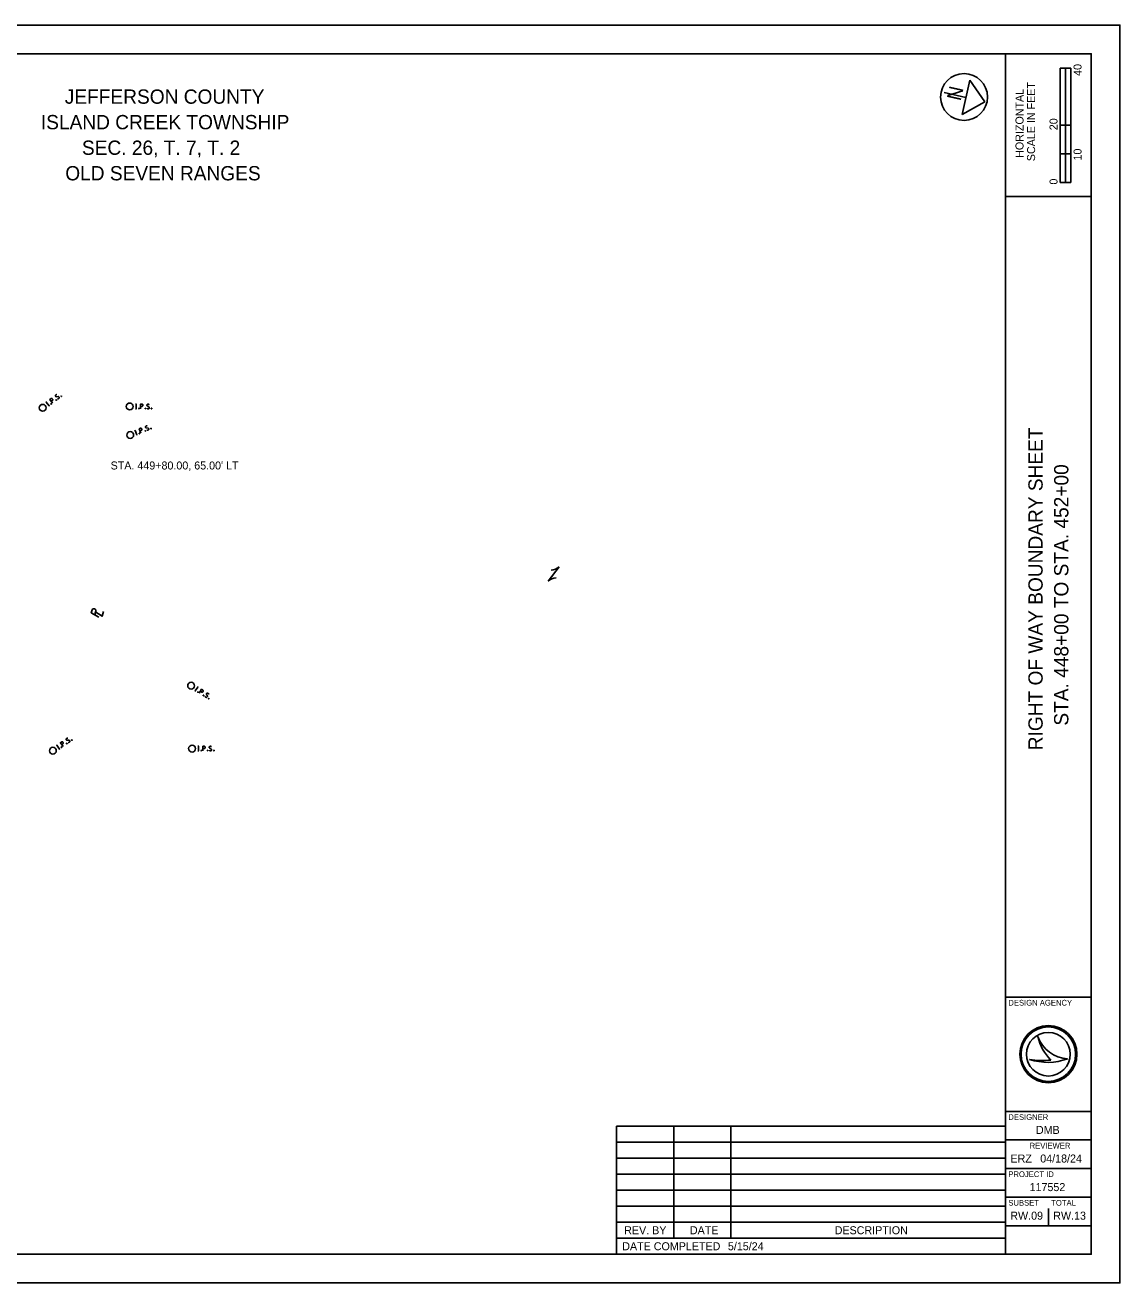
# Model space of a CAD drawing. Extents: x 0 to 116195, y -227 to 408682.
# Drawn here: x 297.1 to 680, y 0 to 440 of the extents above; entities that cross this region are included whole.
import ezdxf

# ---------------------------------------------------------------- set-up
doc = ezdxf.new("R2010")
doc.units = 0
for name, color, linetype in [('_CIVIL_CONSTRUCTION', 7, 'Continuous'), ('CM_Corridor_Final', 7, 'Continuous'), ('CM_Corridor_Range_Final', 7, 'Continuous'), ('MD_P_ACB_B', 7, 'Continuous'), ('MD_P_ACB_T', 7, 'Continuous'), ('MD_P_ACIC_B', 7, 'Continuous'), ('PV_P_EOP', 7, 'Continuous')]:
    doc.layers.add(name, color=color, linetype=linetype)

msp = doc.modelspace()

# ---------------------------------------------------------------- linework, layer by layer
at = {"layer": '_CIVIL_CONSTRUCTION'}
msp.add_lwpolyline([(0, 0), (680, 0), (680, 440), (0, 440)], close=True, dxfattribs=at)
at = {"layer": 'CM_Corridor_Final'}
for p, q in [((659.13, 385), (659.13, 425)), ((662.88, 425), (659.13, 425)), ((659.13, 405), (659.13, 425)), ((659.13, 425), (661, 425)), ((661, 425), (661.02, 425)), ((661.02, 425), (661.02, 405)), ((662.88, 425), (662.88, 385)), ((661.02, 405), (659.13, 405)), ((662.87, 405), (661, 405)), ((661, 405), (661, 395)), ((662.87, 395), (662.87, 405)), ((661, 395), (659.13, 395)), ((659.13, 395), (659.13, 385)), ((661, 385), (661, 395)), ((661, 395), (662.87, 395)), ((662.88, 385), (659.13, 385)), ((659.13, 385), (661, 385)), ((651.35, 86.19), (651.35, 86.19)), ((655, 80), (655, 80)), ((648.34, 78.19), (648.34, 78.19)), ((661.75, 78.37), (661.75, 78.37)), ((655, 20), (655, 26))]:
    msp.add_line(p, q, dxfattribs=at)
for radius in [10, 9.54, 9.54, 7.64]:
    msp.add_circle((655, 80), radius, dxfattribs=at)
for centre, radius, start, end in [((662.32, 89.95), 11.6, 198.9257, 198.9319), ((666.93, 89.4), 15.91, 191.6379, 191.6421), ((662.32, 89.95), 11.6, 198.9319, 267.1657), ((666.93, 89.4), 15.91, 191.6421, 226.0947), ((654.79, 97.4), 20.26, 251.4576, 290.0832), ((652.96, 103.09), 25.32, 259.4964, 259.4995), ((654.79, 97.4), 20.26, 251.4527, 251.4576), ((652.96, 103.09), 25.32, 259.4995, 276.6672)]:
    msp.add_arc(centre, radius, start, end, dxfattribs=at)
at = {"layer": 'CM_Corridor_Range_Final'}
for p, q in [((640, 10), (640, 430)), ((640, 380), (670, 380)), ((640, 100), (670, 100)), ((640, 60), (670, 60)), ((640, 50), (670, 50)), ((640, 40), (670, 40)), ((640, 30), (670, 30)), ((640, 20), (670, 20))]:
    msp.add_line(p, q, dxfattribs=at)
msp.add_lwpolyline([(30, 430), (670, 430), (670, 10), (30, 10)], close=True, dxfattribs=at)
at = {"layer": 'MD_P_ACB_B'}
msp.add_circle((625.5, 414.86), 8.2, dxfattribs=at)
at = {"layer": 'MD_P_ACB_T'}
for p, q in [((480.03, 245.5), (483.84, 250.45)), ((481.93, 247.98), (481.93, 247.98)), ((321.39, 233.7), (321.77, 234.94)), ((322.22, 234.28), (322.22, 234.28))]:
    msp.add_line(p, q, dxfattribs=at)
for points in [[(322.79, 232.83), (320.18, 234.45), (320.49, 235.43)], [(321.38, 234.82), (323.97, 233.19), (324.49, 234.86)]]:
    msp.add_lwpolyline(points, dxfattribs=at)
for centre, radius, start, end in [((483.35, 241.33), 5.34, 95.9058, 128.5484), ((480.51, 254.63), 5.34, 275.9058, 308.5484), ((321.11, 235.13), 0.69, 343.4196, 154.2767)]:
    msp.add_arc(centre, radius, start, end, dxfattribs=at)
at = {"layer": 'MD_P_ACIC_B'}
for p, q in [((627.48, 420.72), (624.79, 408.71)), ((632.8, 413.22), (627.48, 420.72)), ((626.14, 414.71), (618.59, 416.41)), ((624.79, 408.71), (632.8, 413.22)), ((503.93, 54.8), (503.93, 10)), ((503.93, 54.8), (640, 54.8)), ((523.93, 54.8), (523.93, 15.6)), ((543.93, 54.8), (543.93, 15.6)), ((503.93, 49.2), (640, 49.2)), ((503.93, 43.6), (640, 43.6)), ((503.93, 38), (640, 38)), ((503.93, 32.4), (640, 32.4)), ((503.93, 26.8), (640, 26.8)), ((503.93, 21.2), (640, 21.2)), ((503.93, 15.6), (640, 15.6)), ((640, 10), (640, 10))]:
    msp.add_line(p, q, dxfattribs=at)
msp.add_circle((625.5, 414.86), 8.2, dxfattribs=at)
at = {"layer": 'PV_P_EOP'}
for points in [[(304.31, 307.99), (304.59, 308.21)], [(305.42, 306.82), (304.45, 308.1)], [(306.67, 307.77), (305.7, 309.04), (306.12, 309.36), (306.17, 309.39), (306.25, 309.41), (306.29, 309.41), (306.33, 309.41), (306.41, 309.39), (306.47, 309.36), (306.55, 309.29), (306.64, 309.17), (306.66, 309.12), (306.69, 309.05), (306.71, 308.95), (306.7, 308.9), (306.68, 308.86), (306.66, 308.8), (306.59, 308.74), (306.17, 308.42)], [(308.17, 310.77), (308.14, 310.77), (308.09, 310.77), (307.99, 310.75), (307.88, 310.69), (307.81, 310.64), (307.78, 310.62), (307.69, 310.5), (307.64, 310.37), (307.64, 310.24), (307.68, 310.15), (307.73, 310.09), (307.81, 310.02), (307.93, 310), (308.64, 310.07), (308.72, 310.06), (308.76, 310.03), (308.83, 309.99), (308.87, 309.93), (308.91, 309.86), (308.93, 309.81), (308.95, 309.75), (308.97, 309.7), (308.97, 309.65), (308.97, 309.6), (308.96, 309.56), (308.94, 309.52), (308.92, 309.49), (308.85, 309.42), (308.72, 309.32), (308.63, 309.28), (308.46, 309.27), (308.34, 309.27)], [(307.85, 308.93), (307.89, 308.96), (307.93, 308.96), (307.99, 308.94), (308.03, 308.89), (308.03, 308.83), (308.02, 308.79), (307.98, 308.76), (307.93, 308.76), (307.88, 308.78), (307.84, 308.83), (307.83, 308.89), (307.85, 308.93)], [(309.59, 310.25), (309.63, 310.28), (309.67, 310.28), (309.73, 310.26), (309.77, 310.21), (309.77, 310.15), (309.76, 310.11), (309.72, 310.07), (309.67, 310.07), (309.62, 310.1), (309.58, 310.15), (309.58, 310.21), (309.59, 310.25)], [(305.28, 306.72), (305.56, 306.93)], [(306.05, 307.57), (306.1, 307.61), (306.14, 307.61), (306.19, 307.59), (306.23, 307.53), (306.24, 307.47), (306.23, 307.43), (306.18, 307.4), (306.14, 307.4), (306.08, 307.42), (306.05, 307.47), (306.04, 307.53), (306.05, 307.57)], [(335.66, 307.4), (336.01, 307.4)], [(335.66, 305.8), (336.01, 305.8)], [(335.84, 305.8), (335.84, 307.4)], [(336.8, 306.01), (336.85, 306.01), (336.88, 305.99), (336.92, 305.94), (336.92, 305.87), (336.88, 305.82), (336.85, 305.8), (336.8, 305.8), (336.76, 305.82), (336.73, 305.87), (336.73, 305.94), (336.76, 305.99), (336.8, 306.01)], [(337.4, 305.8), (337.4, 307.4), (337.93, 307.4), (337.99, 307.38), (338.06, 307.36), (338.1, 307.33), (338.13, 307.31), (338.17, 307.25), (338.21, 307.18), (338.23, 307.08), (338.23, 306.93), (338.22, 306.88), (338.2, 306.8), (338.15, 306.72), (338.11, 306.68), (338.07, 306.65), (338.02, 306.63), (337.93, 306.62), (337.4, 306.62)], [(339.04, 306.01), (339.1, 306.01), (339.13, 305.99), (339.17, 305.94), (339.17, 305.87), (339.13, 305.82), (339.1, 305.8), (339.04, 305.8), (339.01, 305.82), (338.98, 305.87), (338.98, 305.94), (339.01, 305.99), (339.04, 306.01)], [(340.41, 307.28), (340.39, 307.31), (340.36, 307.33), (340.26, 307.37), (340.14, 307.4), (340.05, 307.4), (340.01, 307.4), (339.87, 307.36), (339.75, 307.28), (339.67, 307.18), (339.65, 307.08), (339.65, 307.01), (339.67, 306.91), (339.76, 306.82), (340.37, 306.44), (340.42, 306.39), (340.44, 306.34), (340.47, 306.26), (340.47, 306.19), (340.45, 306.11), (340.44, 306.06), (340.42, 306), (340.4, 305.95), (340.38, 305.91), (340.34, 305.87), (340.31, 305.85), (340.27, 305.82), (340.23, 305.81), (340.14, 305.8), (339.98, 305.8), (339.88, 305.82), (339.74, 305.91), (339.65, 305.99)], [(341.23, 306.01), (341.28, 306.01), (341.31, 305.99), (341.35, 305.94), (341.35, 305.87), (341.31, 305.82), (341.28, 305.8), (341.23, 305.8), (341.19, 305.82), (341.16, 305.87), (341.16, 305.94), (341.19, 305.99), (341.23, 306.01)], [(339.79, 299.82), (339.76, 299.83), (339.72, 299.84), (339.61, 299.84), (339.49, 299.82), (339.41, 299.78), (339.38, 299.77), (339.26, 299.68), (339.18, 299.56), (339.14, 299.44), (339.16, 299.34), (339.19, 299.27), (339.25, 299.18), (339.36, 299.14), (340.07, 299.02), (340.14, 298.99), (340.18, 298.96), (340.23, 298.89), (340.26, 298.82), (340.27, 298.75), (340.28, 298.7), (340.29, 298.63), (340.29, 298.58), (340.28, 298.53), (340.26, 298.49), (340.24, 298.45), (340.21, 298.41), (340.19, 298.39), (340.1, 298.34), (339.96, 298.28), (339.86, 298.26), (339.69, 298.29), (339.58, 298.33)], [(335.35, 298.11), (335.68, 298.24)], [(336.13, 296.7), (335.51, 298.17)], [(335.96, 296.63), (336.29, 296.76)], [(336.93, 297.26), (336.98, 297.28), (337.02, 297.27), (337.07, 297.24), (337.1, 297.18), (337.08, 297.12), (337.06, 297.08), (337.01, 297.06), (336.97, 297.07), (336.92, 297.11), (336.9, 297.16), (336.91, 297.22), (336.93, 297.26)], [(337.57, 297.29), (336.96, 298.77), (337.45, 298.97), (337.51, 298.98), (337.59, 298.99), (337.63, 298.98), (337.67, 298.97), (337.73, 298.93), (337.79, 298.88), (337.85, 298.8), (337.9, 298.66), (337.91, 298.61), (337.92, 298.53), (337.91, 298.43), (337.89, 298.38), (337.87, 298.34), (337.83, 298.3), (337.75, 298.25), (337.26, 298.05)], [(339.01, 298.12), (339.06, 298.14), (339.1, 298.13), (339.15, 298.09), (339.17, 298.04), (339.16, 297.98), (339.14, 297.94), (339.09, 297.92), (339.05, 297.93), (339, 297.96), (338.98, 298.02), (338.99, 298.08), (339.01, 298.12)], [(341.03, 298.95), (341.08, 298.97), (341.12, 298.96), (341.17, 298.93), (341.19, 298.87), (341.18, 298.81), (341.16, 298.77), (341.11, 298.75), (341.07, 298.76), (341.02, 298.8), (340.99, 298.86), (341.01, 298.92), (341.03, 298.95)], [(356.43, 207.18), (356.73, 206.99)], [(356.58, 207.09), (357.41, 208.45)], [(357.26, 208.55), (357.56, 208.36)], [(357.92, 206.27), (358.75, 207.64), (359.2, 207.37), (359.24, 207.33), (359.29, 207.27), (359.31, 207.23), (359.32, 207.19), (359.33, 207.11), (359.33, 207.04), (359.29, 206.94), (359.21, 206.81), (359.18, 206.78), (359.12, 206.72), (359.04, 206.67), (358.98, 206.66), (358.94, 206.66), (358.88, 206.66), (358.8, 206.7), (358.34, 206.97)], [(357.51, 206.77), (357.56, 206.74), (357.57, 206.7), (357.58, 206.64), (357.54, 206.59), (357.49, 206.56), (357.45, 206.56), (357.4, 206.59), (357.38, 206.63), (357.38, 206.69), (357.42, 206.74), (357.47, 206.77), (357.51, 206.77)], [(359.43, 205.6), (359.48, 205.58), (359.5, 205.54), (359.5, 205.48), (359.46, 205.42), (359.41, 205.4), (359.37, 205.39), (359.32, 205.42), (359.31, 205.46), (359.3, 205.52), (359.34, 205.57), (359.39, 205.6), (359.43, 205.6)], [(361.26, 205.98), (361.26, 206.02), (361.24, 206.05), (361.18, 206.14), (361.09, 206.22), (361.01, 206.27), (360.98, 206.29), (360.84, 206.33), (360.7, 206.33), (360.58, 206.28), (360.51, 206.21), (360.47, 206.14), (360.43, 206.04), (360.46, 205.92), (360.79, 205.28), (360.81, 205.21), (360.8, 205.16), (360.78, 205.08), (360.74, 205.02), (360.69, 204.96), (360.66, 204.92), (360.6, 204.88), (360.56, 204.85), (360.52, 204.83), (360.47, 204.81), (360.43, 204.81), (360.38, 204.81), (360.35, 204.81), (360.25, 204.86), (360.12, 204.94), (360.05, 205.01), (359.97, 205.16), (359.94, 205.27)], [(361.3, 204.47), (361.35, 204.44), (361.36, 204.4), (361.36, 204.34), (361.33, 204.29), (361.28, 204.26), (361.23, 204.26), (361.19, 204.29), (361.17, 204.33), (361.17, 204.39), (361.2, 204.44), (361.26, 204.47), (361.3, 204.47)], [(310.3, 187.65), (309.39, 188.96), (309.83, 189.26), (309.88, 189.29), (309.96, 189.31), (310, 189.31), (310.04, 189.3), (310.11, 189.28), (310.18, 189.24), (310.25, 189.17), (310.34, 189.05), (310.36, 189), (310.38, 188.93), (310.4, 188.83), (310.38, 188.77), (310.37, 188.73), (310.34, 188.68), (310.27, 188.62), (309.83, 188.32)], [(311.94, 190.57), (311.91, 190.58), (311.86, 190.58), (311.76, 190.56), (311.65, 190.51), (311.57, 190.46), (311.55, 190.44), (311.45, 190.33), (311.39, 190.2), (311.39, 190.07), (311.42, 189.98), (311.47, 189.92), (311.54, 189.84), (311.67, 189.82), (312.38, 189.85), (312.45, 189.84), (312.5, 189.81), (312.56, 189.76), (312.6, 189.7), (312.64, 189.63), (312.66, 189.59), (312.67, 189.52), (312.68, 189.47), (312.69, 189.42), (312.68, 189.37), (312.67, 189.33), (312.65, 189.29), (312.63, 189.26), (312.55, 189.19), (312.42, 189.11), (312.33, 189.07), (312.16, 189.06), (312.05, 189.07)], [(313.33, 189.99), (313.38, 190.02), (313.42, 190.02), (313.47, 189.99), (313.51, 189.94), (313.51, 189.88), (313.5, 189.84), (313.45, 189.81), (313.41, 189.81), (313.35, 189.84), (313.32, 189.89), (313.32, 189.95), (313.33, 189.99)], [(307.96, 187.98), (308.25, 188.18)], [(309.01, 186.76), (308.1, 188.08)], [(308.86, 186.66), (309.15, 186.86)], [(309.68, 187.48), (309.72, 187.51), (309.76, 187.51), (309.82, 187.49), (309.86, 187.43), (309.86, 187.37), (309.84, 187.33), (309.8, 187.3), (309.76, 187.3), (309.7, 187.33), (309.67, 187.38), (309.66, 187.44), (309.68, 187.48)], [(311.53, 188.75), (311.58, 188.78), (311.62, 188.78), (311.67, 188.76), (311.71, 188.71), (311.71, 188.65), (311.7, 188.61), (311.65, 188.58), (311.61, 188.58), (311.56, 188.6), (311.52, 188.65), (311.52, 188.71), (311.53, 188.75)], [(357.47, 187.71), (357.82, 187.71)], [(357.47, 186.11), (357.82, 186.11)], [(357.64, 186.11), (357.64, 187.71)], [(358.6, 186.33), (358.66, 186.33), (358.69, 186.3), (358.73, 186.25), (358.73, 186.19), (358.69, 186.14), (358.66, 186.11), (358.6, 186.11), (358.57, 186.14), (358.54, 186.19), (358.54, 186.25), (358.57, 186.3), (358.6, 186.33)], [(359.21, 186.11), (359.21, 187.71), (359.74, 187.71), (359.79, 187.7), (359.87, 187.67), (359.9, 187.65), (359.94, 187.62), (359.98, 187.56), (360.02, 187.5), (360.04, 187.4), (360.04, 187.25), (360.03, 187.2), (360, 187.12), (359.96, 187.03), (359.92, 186.99), (359.88, 186.97), (359.83, 186.94), (359.74, 186.93), (359.21, 186.93)], [(360.85, 186.33), (360.91, 186.33), (360.94, 186.3), (360.97, 186.25), (360.97, 186.19), (360.94, 186.14), (360.91, 186.11), (360.85, 186.11), (360.82, 186.14), (360.79, 186.19), (360.79, 186.25), (360.82, 186.3), (360.85, 186.33)], [(362.22, 187.6), (362.2, 187.62), (362.16, 187.65), (362.07, 187.69), (361.94, 187.71), (361.86, 187.71), (361.82, 187.71), (361.68, 187.67), (361.56, 187.6), (361.48, 187.5), (361.46, 187.4), (361.46, 187.32), (361.48, 187.22), (361.57, 187.13), (362.18, 186.75), (362.23, 186.7), (362.25, 186.65), (362.27, 186.58), (362.27, 186.5), (362.26, 186.43), (362.25, 186.38), (362.23, 186.31), (362.21, 186.26), (362.19, 186.23), (362.15, 186.19), (362.12, 186.16), (362.08, 186.14), (362.04, 186.12), (361.94, 186.11), (361.79, 186.11), (361.69, 186.14), (361.55, 186.23), (361.46, 186.3)], [(363.04, 186.33), (363.09, 186.33), (363.12, 186.3), (363.16, 186.25), (363.16, 186.19), (363.12, 186.14), (363.09, 186.11), (363.04, 186.11), (363, 186.14), (362.97, 186.19), (362.97, 186.25), (363, 186.3), (363.04, 186.33)]]:
    msp.add_lwpolyline(points, dxfattribs=at)
for centre in [(303.18, 306.14), (333.64, 306.59), (333.79, 296.6), (355.12, 208.91), (306.75, 186.18), (355.45, 186.91)]:
    msp.add_circle(centre, 1.2, dxfattribs=at)

# ---------------------------------------------------------------- texts
at = {"layer": 'CM_Corridor_Final'}
for s, height, p in [('40', 2.8, (666.61, 422.25)), ('SCALE IN FEET', 2.8, (650.35, 392.41)), ('HORIZONTAL', 2.8, (646.3, 393.58)), ('20', 2.8, (658.21, 403.25)), ('10', 2.8, (666.61, 392.65)), ('0', 2.8, (658.21, 384.23)), ('RIGHT OF WAY BOUNDARY SHEET', 5, (653, 186.33)), ('STA. 448+00 TO STA. 452+00', 5, (662, 194.94))]:
    msp.add_text(s, height=height, rotation=90, dxfattribs=at).set_placement(p)
for s, height, p in [('             JEFFERSON COUNTY             ', 5, (286.77, 412.5)), ('           ISLAND CREEK TOWNSHIP          ', 5, (282.12, 403.57)), ('            SEC. 26, T. 7, T. 2           ', 5, (294.62, 394.63)), ('             OLD SEVEN RANGES             ', 5, (286.93, 385.7)), ('DESIGN AGENCY', 2, (641, 97)), ('DESIGNER', 2, (641, 57)), ('DMB', 2.8, (650.65, 52.1)), ('REVIEWER', 2, (648.44, 47)), ('ERZ', 2.8, (641.74, 42.1)), ('04/18/24', 2.8, (652.16, 42.1)), ('PROJECT ID', 2, (641, 37)), ('117552', 2.8, (648.42, 32.1)), ('SUBSET', 2, (641, 27)), ('TOTAL', 2, (656, 27)), ('RW.09', 2.8, (641.68, 22.1)), ('RW.13', 2.8, (656.7, 22.1))]:
    msp.add_text(s, height=height, dxfattribs=at).set_placement(p)
at = {"layer": 'MD_P_ACIC_B'}
msp.add_text('N', height=5, rotation=257.36, dxfattribs=at).set_placement((620.48, 419.08))
for s, p in [("STA. 449+80.00, 65.00' LT", (326.95, 284.55)), ('REV. BY', (506.61, 17)), ('DATE', (529.59, 17)), ('DESCRIPTION', (580.25, 17)), ('DATE COMPLETED', (505.93, 11.4)), ('5/15/24                            ', (542.89, 11.4))]:
    msp.add_text(s, height=2.8, dxfattribs=at).set_placement(p)

doc.saveas('drawing.dxf')
